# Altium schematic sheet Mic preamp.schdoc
size 175 x 143 mm
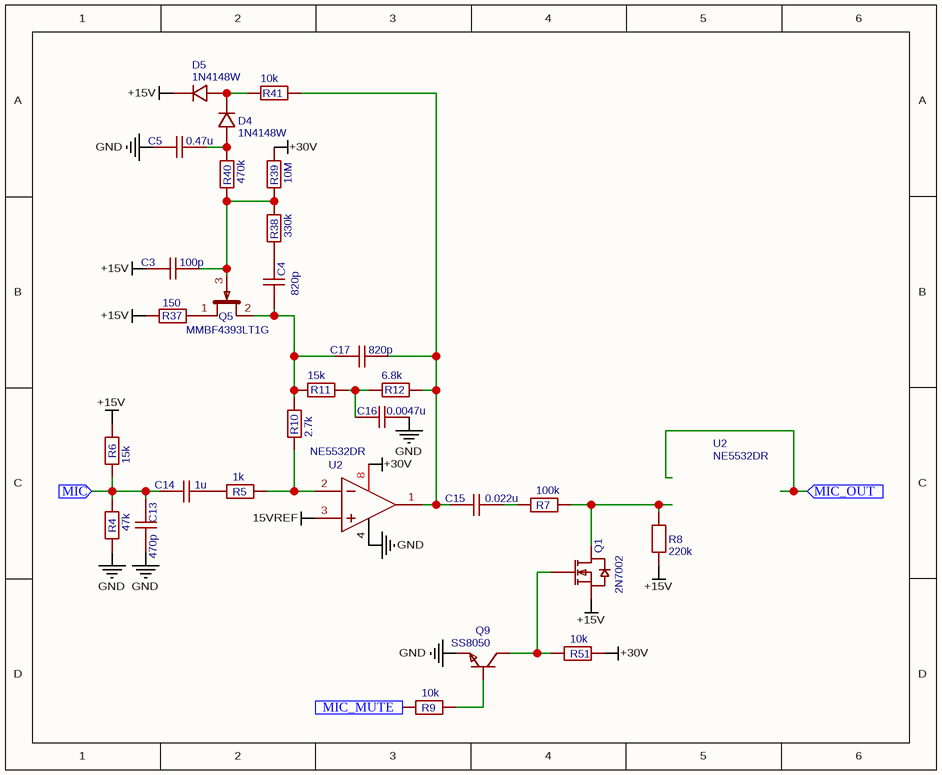
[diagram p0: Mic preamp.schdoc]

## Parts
(Parts that share a designator on the sheet are numbered #1, #2 ... from top to bottom, then left to right.)
C3  100p  [C0805]
C4  820p  [C1206]
C5  0.47u  [C0805]
C13  470p  [C0805]
C14  1u  [C1206]
C15  0.022u  [C0805]
C16  0.0047u  [C0805]
C17  820p  [C1206]
D4  1N4148W  [SOD-123FL_L2.6-W1.6-LS3.4-RD]
D5  1N4148W  [SOD-123FL_L2.6-W1.6-LS3.4-RD]
Q1  2N7002  [SOT-23-3_L2.9-W1.3-P1.90-LS2.4-BR]
Q5  MMBF4393LT1G  [SOT-23-3_L2.9-W1.3-P1.90-LS2.4-BR]
Q9  SS8050  [SOT-23-3_L2.9-W1.3-P1.90-LS2.4-BR]
R4  47k  [R0805]
R5  1k  [R1206]
R6  15k  [R0805]
R7  100k  [R1206]
R8  220k  [R0805]
R9  10k  [R1206]
R10  2.7k  [R0805]
R11  15k  [R0805]
R12  6.8k  [R0805]
R37  150  [R0805]
R38  330k  [R0805]
R39  10M  [R0805]
R40  470k  [R0805]
R41  10k  [R1206]
R51  10k  [R1206]
U2#1  NE5532DR  [SOIC-8_L4.9-W3.9-P1.27-LS6.0-BL]
U2#2  NE5532DR  [SOIC-8_L4.9-W3.9-P1.27-LS6.0-BL]

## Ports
MIC (in), MIC_MUTE (in), MIC_OUT (in)

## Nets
15VREF: U2#2.3(IN1+)
+15V: C3.1 D5.1 Q1.2(S) R6.2 R8.1 R37.2
+30V: R39.1 R51.2 U2#2.8(VCC+)
GND: C5.1 C13.1 C16.2 Q9.2(E) R4.1 U2#2.4(VCC-/GND)
MIC: C13.2 C14.1 R4.2 R6.1 ; port MIC
MIC_MUTE: R9.1 ; port MIC_MUTE
NetC3_2: C3.2 Q5.3(G) R38.1 R39.2 R40.2
NetC4_1: C4.1 C17.1 Q5.2(S) R10.2 R11.2
NetC4_2: C4.2 R38.2
NetC5_2: C5.2 D4.2 R40.1
NetC14_2: C14.2 R5.1
NetC15_1: C15.1 C17.2 R12.1 R41.2 U2#2.1(OUT1)
NetC15_2: C15.2 R7.1
NetC16_1: C16.1 R11.1 R12.2
NetD4_1: D4.1 D5.2 R41.1
NetQ1_1: Q1.1(G) Q9.3(C) R51.1
NetQ1_3: Q1.3(D) R7.2 R8.2
NetQ5_1: Q5.1(D) R37.1
NetQ9_1: Q9.1(B) R9.2
NetR5_2: R5.2 R10.1 U2#2.2(IN1-)

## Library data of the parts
C3 = 100p: BOM_Manufacturer Part: CL21C101JBANNNC; BOM_Manufacturer: SAMSUNG(三星); nameAlias: Value(F); Contributor: LCEDA_Lib
C4 C17 = 820p: BOM_Manufacturer Part: 1206B102K202NT; BOM_Manufacturer: FH(风华); nameAlias: Value(F); Contributor: LCEDA_Lib
C5 = 0.47u: BOM_Manufacturer Part: CL21B474KBFNNNE; BOM_Manufacturer: SAMSUNG(三星); nameAlias: Value(F); Contributor: LCEDA_Lib
C13 = 470p: nameAlias: Value(F); Contributor: LCEDA_Lib
C14 = 1u: BOM_Manufacturer Part: CL31B105KBHNNNE; BOM_Manufacturer: SAMSUNG(三星); nameAlias: Value(F); Contributor: LCEDA_Lib
C15 = 0.022u: BOM_Manufacturer Part: CL21B223KBANNNC; BOM_Manufacturer: SAMSUNG(三星); nameAlias: Value(F); Contributor: LCEDA_Lib
C16 = 0.0047u: BOM_Manufacturer Part: 0805B472K500NT; BOM_Manufacturer: FH(风华); nameAlias: Value(F); Contributor: LCEDA_Lib
D4 D5 = 1N4148W: BOM_Manufacturer: Tak Cheong; Contributor: LCEDA_Lib
Q1 = 2N7002: BOM_Manufacturer: CJ(江苏长电/长晶)
Q5 = MMBF4393LT1G: BOM_Manufacturer: onsemi(安森美); Contributor: LCSC
Q9 = SS8050: BOM_Manufacturer: CJ(江苏长电/长晶)
R4 = 47k: BOM_Manufacturer Part: 0805W8F4702T5E; BOM_Manufacturer: UNI-ROYAL(厚声); nameAlias: Value(Ω); Contributor: LCEDA_Lib
R5 = 1k: BOM_Manufacturer Part: 1206W4F1001T5E; BOM_Manufacturer: UNI-ROYAL(厚声); nameAlias: Value(Ω); Contributor: LCEDA_Lib
R6 R11 = 15k: BOM_Manufacturer Part: 0805W8F1502T5E; BOM_Manufacturer: UNI-ROYAL(厚声); nameAlias: Value(Ω); Contributor: LCEDA_Lib
R7 = 100k: BOM_Manufacturer Part: 1206W4F1003T5E; BOM_Manufacturer: UNI-ROYAL(厚声); nameAlias: Value(Ω); Contributor: LCEDA_Lib
R8 = 220k: BOM_Manufacturer Part: 0805W8F2203T5E; BOM_Manufacturer: UNI-ROYAL(厚声); nameAlias: Value(Ω); Contributor: LCEDA_Lib
R9 R41 R51 = 10k: BOM_Manufacturer Part: 1206W4F1002T5E; BOM_Manufacturer: UNI-ROYAL(厚声); nameAlias: Value(Ω); Contributor: LCEDA_Lib
R10 = 2.7k: BOM_Manufacturer Part: 0805W8F2701T5E; nameAlias: Value(Ω); Contributor: LCEDA_Lib
R12 = 6.8k: BOM_Manufacturer Part: 0805W8F6801T5E; BOM_Manufacturer: UNI-ROYAL(厚声); nameAlias: Value(Ω); Contributor: LCEDA_Lib
R37 = 150: BOM_Manufacturer Part: 0805W8F1500T5E; BOM_Manufacturer: UNI-ROYAL(厚声); nameAlias: Value(Ω); Contributor: LCEDA_Lib
R38 = 330k: BOM_Manufacturer Part: 0805W8F3303T5E; BOM_Manufacturer: UNI-ROYAL(厚声); nameAlias: Value(Ω); Contributor: LCEDA_Lib
R39 = 10M: BOM_Manufacturer Part: 0805W8F1005T5E; BOM_Manufacturer: UNI-ROYAL(厚声); nameAlias: Value(Ω); Contributor: LCEDA_Lib
R40 = 470k: BOM_Manufacturer Part: 0805W8F4703T5E; BOM_Manufacturer: UNI-ROYAL(厚声); nameAlias: Value(Ω); Contributor: LCEDA_Lib
U2#1 U2#2 = NE5532DR: BOM_Manufacturer: TI(德州仪器); subpart_no: 2; SMT Type: Basic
